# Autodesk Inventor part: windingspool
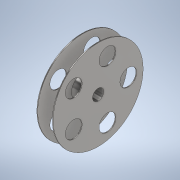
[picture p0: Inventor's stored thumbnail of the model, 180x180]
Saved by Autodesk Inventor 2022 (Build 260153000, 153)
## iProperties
Created: 2021-06
Part Number: windingspool
Material: Generic
Document SubType Name: Modeling
Designer: Chimms
Density: 1 g/cm^3
Appearance: Steel - Polished
Author: Chimms
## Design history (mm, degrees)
sketch "Sketch1"
  geometry: C1 r 40 at (0, 0); C2 r 5 at (0, 0); C3 r 10 at (0, 0); 1 further point
  constraints: 3 centre point, 3 coincident
  dimensions: "d0" = 80 diameter of C1; "d1" = 10 diameter of C2; "d2" = 20 diameter of C3
extrude "Extrusion1" new body sketch "Sketch1" distance "d3" = 0.75; taper "d4" = 0 deg
sketch "Sketch2"
  geometry: C1 r 5 at (0, 0); 1 further point
  constraints: 1 centre point, 1 coincident
  dimensions: "d5" = 10 diameter of C1
sketch "Sketch3"
  geometry: C1 r 10 at (0, 0); 1 further point
  constraints: 1 centre point, 1 coincident
  dimensions: "d6" = 20 diameter of C1
extrude "Extrusion2" join sketch "Sketch3" distance "d7" = 13; taper "d8" = 0 deg
sketch "Sketch4"
  geometry: C1 r 40 at (0, 0); 1 further point
  constraints: 1 centre point, 1 coincident
  dimensions: "d9" = 80 diameter of C1
extrude "Extrusion3" join sketch "Sketch4" distance "d10" = 0.75; taper "d11" = 0 deg
extrude "Extrusion4" cut sketch "Sketch2" extent not by distance; stored distance "d12" = 0; taper "d13" = 0 deg
sketch "Sketch5"
  geometry: C1 r 7.5 at (-26.857, 0); C2 r 7.5 at (-8.299, -25.543); C3 r 7.5 at (21.728, -15.786); C4 r 7.5 at (21.728, 15.786); C5 r 7.5 at (-8.299, 25.543); 5 further points
  constraints: 5 centre point, 2 coincident, 14 other
  dimensions: "d14" = 15 diameter of C1; "d17" = 360 deg dimension on point (0, 0) C1.centre (derived)
extrude "Extrusion5" cut sketch "Sketch5" extent not by distance; stored distance "d19" = 0; taper "d20" = 0 deg
sketch "Sketch6"
  geometry: C1 r 5 at (0, 0) reference; C2 r 10 at (0, 0); 1 further point
  constraints: 1 centre point, 1 coincident
  dimensions: "d21" = 20 diameter of C2
extrude "Extrusion6" join sketch "Sketch6" distance "d22" = 0.75; taper "d23" = 0 deg
body "Solid1"
